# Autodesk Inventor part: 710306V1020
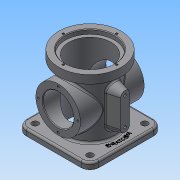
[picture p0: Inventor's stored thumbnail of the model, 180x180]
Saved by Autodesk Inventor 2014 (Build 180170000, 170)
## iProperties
Created: 2021-03
Part Number: 710306V1020
Material: 일반
Document SubType Name: Modeling
Designer: NET
Density: 1 g/cm^3
Appearance: 기본값
Author: NET
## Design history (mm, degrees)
sketch "스케치3"
  geometry: L1 (57, -57)-(-57, -57); L2 (-57, -57)-(-57, 57); L3 (-57, 57)-(57, 57); L4 (57, 57)-(57, -57); L5 (57, -57)-(-57, 57); L6 (-57, -57)-(57, 57); 1 further point
  constraints: 12 end point, 2 midpoint, 2 parallel, 1 horizontal, 1 perpendicular
  dimensions: "d5" = 114 distance of L2.end L3.end; "d6" = 114 distance of L1.end L2.end
extrude "돌출1" new body sketch "스케치3" distance "d7" = 10; taper "d8" = 0 deg
sketch "스케치4"
  geometry: C1 r 38 at (0, 0); 1 further point
  constraints: 1 centre point, 1 coincident
  dimensions: "d9" = 76 diameter of C1
extrude "돌출2" join sketch "스케치4" distance "d10" = 88; taper "d11" = 0 deg
sketch "스케치5"
  geometry: C1 r 38 at (0, 0) reference; C2 r 49 at (0, 0)
  constraints: 1 centre point, 1 coincident
  dimensions: "d12" = 98 diameter of C2
extrude "돌출3" join sketch "스케치5" distance "d13" = 13; taper "d14" = 0 deg
hole "구멍1" diameter "d17" = 77; stored, may be unused: countersink angle "d21" = 90 deg, drill point angle "d23" = 0 deg; dims "d15" = 10, "d16" = 10, "d18" = 6, "d19" = 4, "d20" = 2, "d22" = 7
hole "구멍2" diameter "d26" = 66; stored, may be unused: countersink angle "d30" = 90 deg, drill point angle "d32" = 0 deg; dims "d24" = 10, "d25" = 10, "d27" = 6, "d28" = 4, "d29" = 2, "d31" = 104
node "작업 평면1"
sketch "스케치6"
  geometry: L1 (57, 0)-(-57, 0) reference; C1 r 35 at (0, 54); 2 further points
  constraints: 1 centre point, 1 midpoint, 1 vertical alignment
  dimensions: "d34" = 70 diameter of C1; "d35" = 54 distance from line of C1.centre L1
extrude "돌출4" join sketch "스케치6" stored distance "d36" = 13; taper "d37" = 0 deg
hole "구멍3" diameter "d40" = 48; stored, may be unused: countersink angle "d44" = 90 deg, drill point angle "d46" = 0 deg; dims "d38" = 10, "d39" = 10, "d41" = 6, "d42" = 4, "d43" = 2, "d45" = 30
sketch "스케치7" dims "d47" = 62
  geometry: C1 r 24 at (0, 0) reference; C2 r 35 at (0, 0) reference; 3 further points
  constraints: 2 vertical alignment, 1 coincident, 2 other
hole "구멍4" sketch "스케치7" at (0, 31) diameter "d48" = 3.242; stored, may be unused: countersink angle "d52" = 90 deg, drill point angle "d54" = 118 deg; dims "d49" = 6, "d50" = 4, "d51" = 2, "d53" = 8
fillet "모깎기1" dims "d58" = 14
sketch "스케치8"
  geometry: A1 r 14 centre (-43, 43) between (-43, 57) and (-57, 43) reference; A2 r 14 centre (-43, -43) between (-57, -43) and (-43, -57) reference; A3 r 14 centre (43, -43) between (43, -57) and (57, -43) reference; A4 r 14 centre (43, 43) between (57, 43) and (43, 57) reference
hole "구멍5" sketch "스케치8" at (43, -43), (43, 43), (-43, 43), (-43, -43) diameter "d59" = 10; stored, may be unused: countersink angle "d63" = 90 deg, drill point angle "d65" = 118 deg; dims "d60" = 6, "d61" = 4, "d62" = 2, "d64" = 8
node "작업 평면2"
sketch "스케치9"
  geometry: L1 (0, 75.5)-(0, 32.5); L2 (7, 75.5)-(7, 32.5); L3 (-7, 32.5)-(-7, 75.5); L4 (43, 0)-(-43, 0) reference; A1 r 7 centre (0, 75.5) between (7, 75.5) and (-7, 75.5); A2 r 7 centre (0, 32.5) between (-7, 32.5) and (7, 32.5); 3 further points
  constraints: 8 end point, 4 point on circle, 4 tangent, 2 centre point, 2 midpoint, 1 parallel, 1 vertical, 1 vertical alignment
  dimensions: "d68" = 54 distance from line of L4 point (0, 54); "d69" = 14 distance between parallel lines of L2 L3; "d70" = 43 distance of L1.end L1.start
extrude "돌출5" join sketch "스케치9" stored distance "d71" = 13; taper "d72" = 15 deg
sketch "스케치10"
  geometry: A1 r 7 centre (-75.5, 0) between (-75.5, 7) and (-75.5, -7) reference; A2 r 7 centre (-32.5, 0) between (-32.5, -7) and (-32.5, 7) reference; 1 further point
hole "구멍6" sketch "스케치10" at (-75.5, 0), (-32.5, 0) diameter "d73" = 4.134; stored, may be unused: countersink angle "d77" = 90 deg, drill point angle "d79" = 118 deg; dims "d74" = 8, "d75" = 4, "d76" = 2, "d78" = 10
fillet "모깎기2" dims "d80" = 3
chamfer "모따기1" distance "d81" = 1; stored, may be unused: second distance "d82" = 2, angle "d83" = 45 deg
sketch "스케치11"
  geometry: C1 r 41 at (0, 0) reference; C2 r 50 at (0, 0)
  constraints: 1 centre point, 1 coincident, 1 other
  dimensions: "d84" = 100 diameter of C2
feature "엠보싱1" sketch "스케치11" dims "d5" = 114, "d6" = 114, "d22" = 7, "d85" = 0.5, "d86" = 0
sketch "스케치12" dims "d87" = 84
  geometry: C1 r 49 at (0, 0) reference; C2 r 39.5 at (0, 0) reference; 2 further points
  constraints: 2 horizontal alignment, 1 coincident, 2 other
hole "구멍7" sketch "스케치12" at (-42, 0) diameter "d88" = 3.242; stored, may be unused: countersink angle "d92" = 90 deg, drill point angle "d94" = 118 deg; dims "d89" = 6, "d90" = 4, "d91" = 2, "d93" = 8
node "솔리드1"
pattern_circular "원형 패턴1" dims angle "d56" = 360 deg
mirror "대칭1"
pattern_circular "원형 패턴2" dims angle "d96" = 360 deg
other parameters: "d66" = 55
